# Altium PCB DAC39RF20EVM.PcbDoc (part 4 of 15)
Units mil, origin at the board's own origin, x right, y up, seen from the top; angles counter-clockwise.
Board outline 6200 x 2716.54 mil, 16 copper layers (Top Layer, L2 GND, L3 PWR, L4 GND, L5 PWR, L6 GND, L7 SIG, L8 GND, L9 GND, L10 SIG, L11 GND, L12 PWR, L13 GND, L14 PWR, L15 GND, Bottom Layer), stack 76.97 mil thick; 766 components, 495 nets, 3414 pads, 2373 vias.
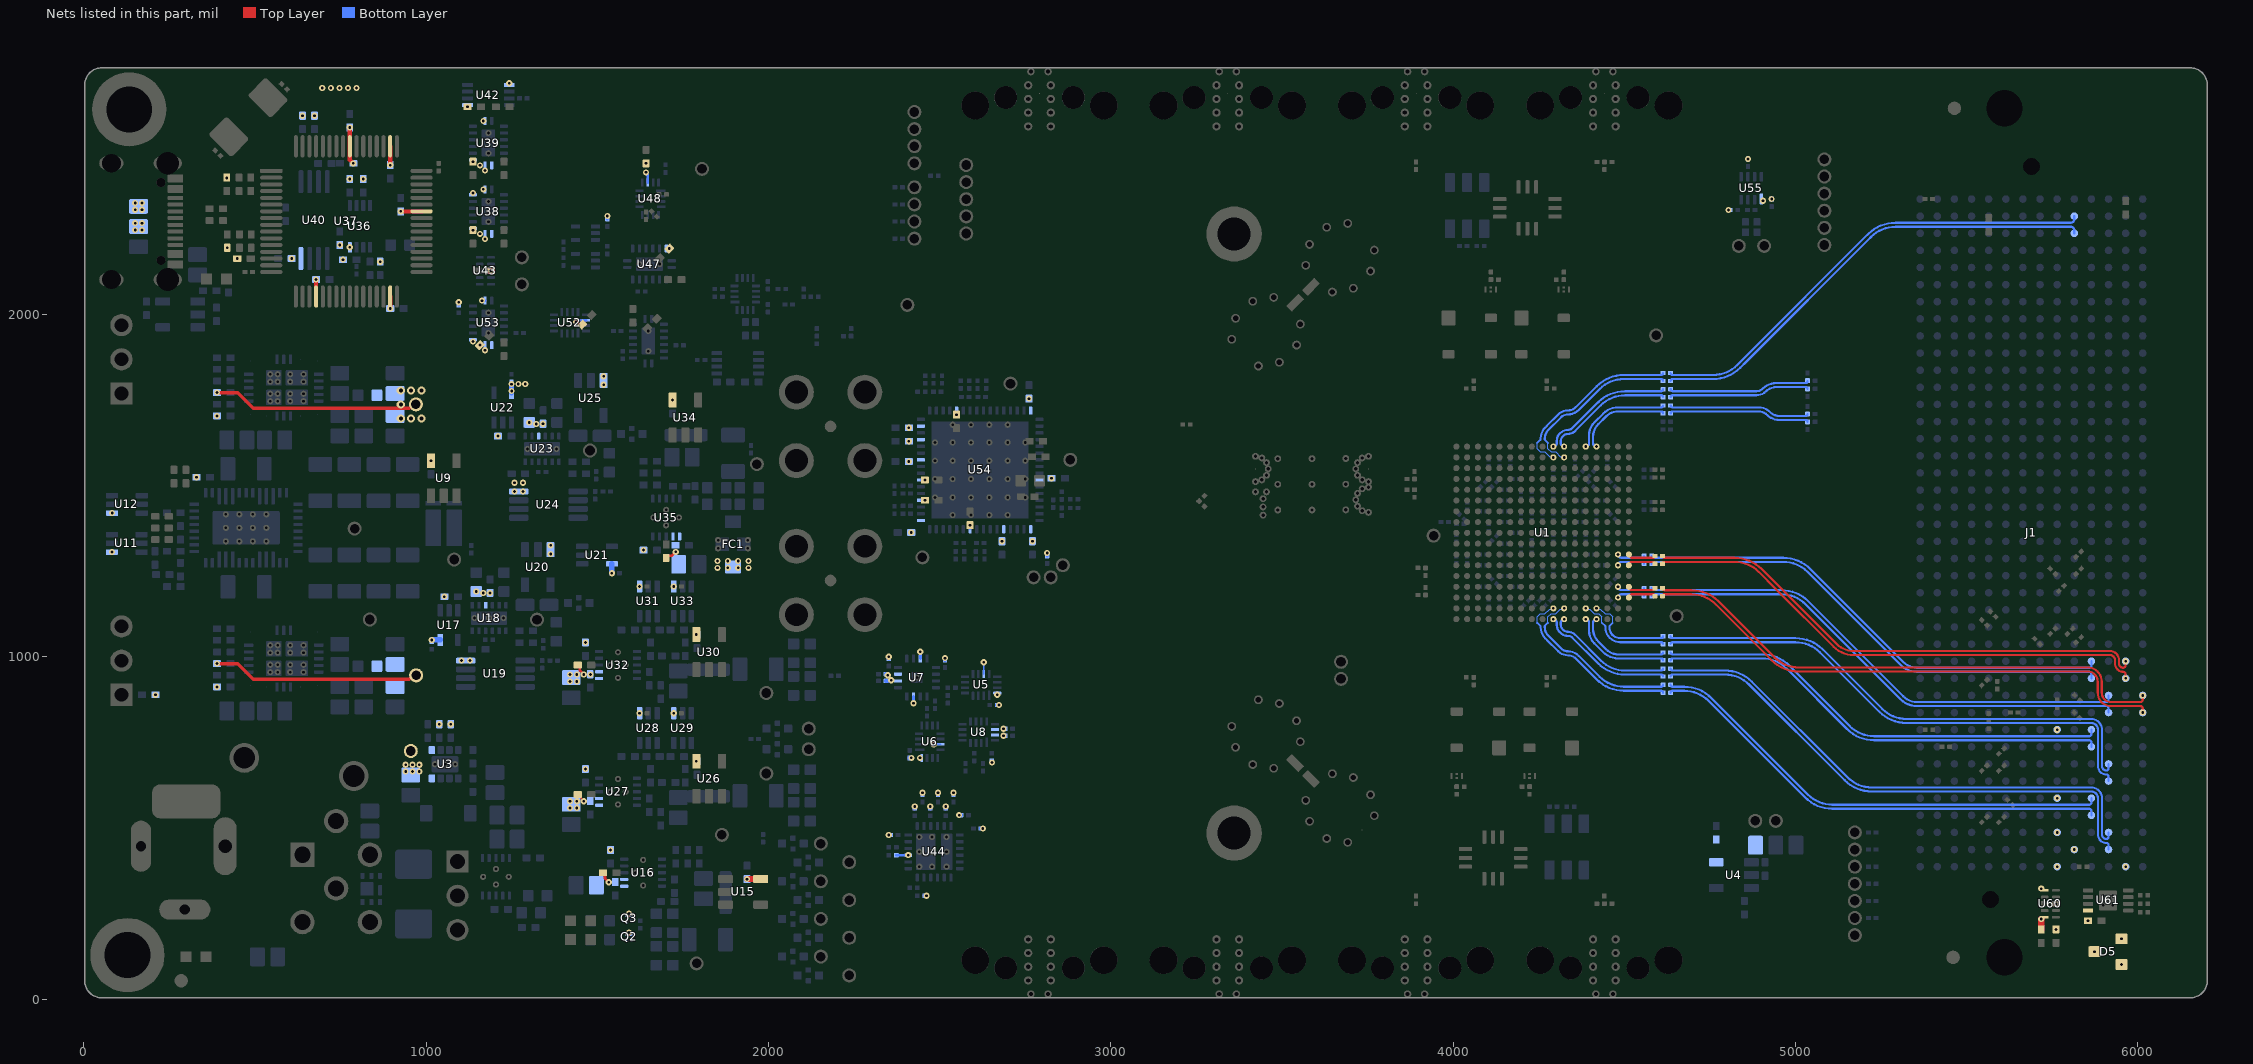
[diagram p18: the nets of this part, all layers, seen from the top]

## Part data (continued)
R6 R7 R104 R115 R116: library part RSMD080510615, "RES SMD 0 OHM JUMPER 1/8W 0805", Manufacturer="Panasonic Electronic Components", Operating Temperature="-55°C ~ 155°C", Power (Watts)="0.125W, 1/8W", Ratings=AEC-Q200, Resistance="0 Ω", Supplier Part Number 1=P0.0ACT-ND, Temperature Coefficient=-, Tolerance=Jumper
R10: library part RSMD040202418, "RES SMD 37.4KOHM 0.1% 1/16W 0402", Manufacturer="Panasonic Electronic Components", Operating Temperature="-55°C ~ 155°C", Power (Watts)="0.063W, 1/16W", Ratings=AEC-Q200, Resistance="37.4 kΩ", Supplier Part Number 1=P37.4KDCCT-ND, Temperature Coefficient=±25ppm/°C, Tolerance=±0.1%
R11: library part RSMD040200519, "RES SMD 12K OHM 1% 1/10W 0402", Manufacturer="Panasonic Electronic Components", Operating Temperature="-55°C ~ 155°C", Power (Watts)="0.1W, 1/10W", Ratings=AEC-Q200, Resistance="12 kΩ", Supplier Part Number 1=P12.0KLCT-ND, Temperature Coefficient=±100ppm/°C, Tolerance=±1%
R12 R16 R22 R43 R58 R66 R67 R78 R89 R178 R180: library part RSMD020100289, "RES SMD 100 OHM 1% 1/20W 0201", Manufacturer="Panasonic Electronic Components", Operating Temperature="-55°C ~ 125°C", Power (Watts)="0.05W, 1/20W", Resistance="100 Ω", Supplier Part Number 1=P122654CT-ND, Temperature Coefficient=±200ppm/°C, Tolerance=±1%
R13 R14 R15 R17 R18 R19 R128 R129 R130 R131 R132 R133 R134 R138 R139 R140 R142 R143 R144 R145 R148 R149 R151 R152 R154 R155 R156: library part RSMD020100762, "RES SMD 10K OHM 1% 1/20W 0201", Manufacturer="Panasonic Electronic Components", Operating Temperature="-55°C ~ 125°C", Power (Watts)="0.05W, 1/20W", Resistance="10 kΩ", Supplier Part Number 1=P122414CT-ND, Temperature Coefficient=±200ppm/°C, Tolerance=±1%
R21: library part RSMD040200358, "RES SMD 100K OHM 1% 1/10W 0402", Manufacturer="Panasonic Electronic Components", Operating Temperature="-55°C ~ 155°C", Power (Watts)="0.1W, 1/10W", Ratings=AEC-Q200, Resistance="100 kΩ", Supplier Part Number 1=P100KLCT-ND, Temperature Coefficient=±100ppm/°C, Tolerance=±1%
R23: library part CMP-0089456-1, "5 mOhms ±1% 1W Chip Resistor Wide 1206 (3216 Metric), 0612 Automotive AEC-Q200, Current Sense Metal Foil", Digikey Part Number=408-1969-1-ND, Manufacturer=Susumu, Mouser Part Number=754-KRL3216TMR005FT1, Operating Temperature Range="-55°C to +155°C", Power_W=1W, TempCo=50ppm/°C, Tolerance_%=1%
R24: library part RSMD040201279, "RES SMD 2.55KOHM 0.1% 1/16W 0402", Manufacturer="Panasonic Electronic Components", Operating Temperature="-55°C ~ 155°C", Power (Watts)="0.063W, 1/16W", Ratings=AEC-Q200, Resistance="2.55 kΩ", Supplier Part Number 1=P17782CT-ND, Temperature Coefficient=±15ppm/°C, Tolerance=±0.1%
R25: library part RSMD040200723, "RES SMD 14K OHM 1% 1/10W 0402", Manufacturer="Panasonic Electronic Components", Operating Temperature="-55°C ~ 155°C", Power (Watts)="0.1W, 1/10W", Ratings=AEC-Q200, Resistance="14 kΩ", Supplier Part Number 1=P14.0KLCT-ND, Temperature Coefficient=±100ppm/°C, Tolerance=±1%
R27: library part RSMD040200350, "RES SMD 10.7K OHM 1% 1/10W 0402", Manufacturer="Panasonic Electronic Components", Operating Temperature="-55°C ~ 155°C", Power (Watts)="0.1W, 1/10W", Ratings=AEC-Q200, Resistance="10.7 kΩ", Supplier Part Number 1=P10.7KLCT-ND, Temperature Coefficient=±100ppm/°C, Tolerance=±1%
R28: library part RSMD040200983, "RES SMD 17.4K OHM 1% 1/10W 0402", Manufacturer="Panasonic Electronic Components", Operating Temperature="-55°C ~ 155°C", Power (Watts)="0.1W, 1/10W", Ratings=AEC-Q200, Resistance="17.4 kΩ", Supplier Part Number 1=P17.4KLCT-ND, Temperature Coefficient=±100ppm/°C, Tolerance=±1%
R29: library part RSMD040201204, "RES SMD 2.2K OHM 0.1% 1/16W 0402", Manufacturer="Panasonic Electronic Components", Operating Temperature="-55°C ~ 155°C", Power (Watts)="0.063W, 1/16W", Ratings=AEC-Q200, Resistance="2.2 kΩ", Supplier Part Number 1=P2.2KCPCT-ND, Temperature Coefficient=±10ppm/°C, Tolerance=±0.1%
R30: library part RSMD040200908, "RES SMD 16.9KOHM 0.1% 1/16W 0402", Manufacturer="Panasonic Electronic Components", Operating Temperature="-55°C ~ 155°C", Power (Watts)="0.063W, 1/16W", Ratings=AEC-Q200, Resistance="16.9 kΩ", Supplier Part Number 1=P17956CT-ND, Temperature Coefficient=±10ppm/°C, Tolerance=±0.1%
R31 R74 R81: library part RSMD040200022, "RES SMD 1M OHM 1% 1/5W 0402", Manufacturer="Panasonic Electronic Components", Operating Temperature="-55°C ~ 155°C", Power (Watts)="0.2W, 1/5W", Ratings=AEC-Q200, Resistance="1 MΩ", Supplier Part Number 1=P17242CT-ND, Temperature Coefficient=±100ppm/°C, Tolerance=±1%
R32: library part RSMD040201457, "RES SMD 22K OHM 0.1% 1/16W 0402", Manufacturer="Panasonic Electronic Components", Operating Temperature="-55°C ~ 155°C", Power (Watts)="0.063W, 1/16W", Ratings=AEC-Q200, Resistance="22 kΩ", Supplier Part Number 1=P22KCNCT-ND, Temperature Coefficient=±15ppm/°C, Tolerance=±0.1%
R35: library part RSMD040203923, "RES SMD 9.31KOHM 0.1% 1/16W 0402", Manufacturer="Panasonic Electronic Components", Operating Temperature="-55°C ~ 155°C", Power (Watts)="0.063W, 1/16W", Ratings=AEC-Q200, Resistance="9.31 kΩ", Supplier Part Number 1=P9.31KDCCT-ND, Temperature Coefficient=±25ppm/°C, Tolerance=±0.1%
R36 R41: library part RSMD040203748, "RES SMD 80.6K OHM 1% 1/10W 0402", Manufacturer="Panasonic Electronic Components", Operating Temperature="-55°C ~ 155°C", Power (Watts)="0.1W, 1/10W", Ratings=AEC-Q200, Resistance="80.6 kΩ", Supplier Part Number 1=P80.6KLCT-ND, Temperature Coefficient=±100ppm/°C, Tolerance=±1%
R37 R42: library part RSMD040202615, "RES SMD 4.87KOHM 0.1% 1/16W 0402", Manufacturer="Panasonic Electronic Components", Operating Temperature="-55°C ~ 155°C", Power (Watts)="0.063W, 1/16W", Ratings=AEC-Q200, Resistance="4.87 kΩ", Supplier Part Number 1=P4.87KDCCT-ND, Temperature Coefficient=±25ppm/°C, Tolerance=±0.1%
R40: library part RSMD040201045, "RES SMD 18.2KOHM 0.1% 1/16W 0402", Manufacturer="Panasonic Electronic Components", Operating Temperature="-55°C ~ 155°C", Power (Watts)="0.063W, 1/16W", Ratings=AEC-Q200, Resistance="18.2 kΩ", Supplier Part Number 1=P17962CT-ND, Temperature Coefficient=±10ppm/°C, Tolerance=±0.1%
R46 R83 R92: library part OtherRs00003, "RES 0.01 OHM 1% 1/3W 0603", Manufacturer="Stackpole Electronics Inc", Operating Temperature="-55°C ~ 150°C", Power (Watts)="0.333W, 1/3W", Ratings=AEC-Q200, Resistance="10 mΩ", Supplier Part Number 1=738-CSS0603FT10L0CT-ND, Temperature Coefficient=±50ppm/°C, Tolerance=±1%
R47 R71 R77 R84 R85: library part RSMD040203878, "RES SMD 88.7KOHM 0.1% 1/16W 0402", Manufacturer="Panasonic Electronic Components", Operating Temperature="-55°C ~ 155°C", Power (Watts)="0.063W, 1/16W", Ratings=AEC-Q200, Resistance="88.7 kΩ", Supplier Part Number 1=P88.7KDCCT-ND, Temperature Coefficient=±25ppm/°C, Tolerance=±0.1%
R48 R94: library part RSMD040200551, "RES SMD 12.4KOHM 0.1% 1/16W 0402", Manufacturer="Panasonic Electronic Components", Operating Temperature="-55°C ~ 155°C", Power (Watts)="0.063W, 1/16W", Ratings=AEC-Q200, Resistance="12.4 kΩ", Supplier Part Number 1=P12.4KDCCT-ND, Temperature Coefficient=±25ppm/°C, Tolerance=±0.1%
R49: library part Resistor, "RES 12K OHM 0.5% 1/10W 0402 SMD", Manufacturer="Panasonic Electronic Components", Operating Temperature="-55°C ~ 155°C", Power (Watts)="0.1W, 1/10W", Ratings=AEC-Q200, Resistance="12 kΩ", Supplier Part Number 1=10-ERJ-U2RD1202XCT-ND, Temperature Coefficient=±50ppm/°C, Tolerance=±0.5%
R50 R76 R88 R96: library part RSMD040200004, "RES 0 OHM JUMPER 0402 SMD", Manufacturer="Panasonic Electronic Components", Operating Temperature="-55°C ~ 155°C", Power (Watts)="0.1W, 1/10W", Ratings=AEC-Q200, Resistance="0 Ω", Supplier Part Number 1=10-ERJ-U020R00XCT-ND, Temperature Coefficient="-100/ +600ppm/°C", Tolerance=Jumper
R51 R55 R59 R63 R169 R170: library part RSMD040200316, "RES 10K OHM 1% 1/10W 0402", Manufacturer="Panasonic Electronic Components", Operating Temperature="-55°C ~ 175°C", Power (Watts)="0.1W, 1/10W", Ratings=AEC-Q200, Resistance="10 kΩ", Supplier Part Number 1=10-ERJ-H2RF1002XCT-ND, Temperature Coefficient=±100ppm/°C, Tolerance=±1%
R52 R60 R70: library part OtherRs00006, "RES 0.005 OHM 1% 1/3W 0603", Manufacturer="Stackpole Electronics Inc", Operating Temperature="-55°C ~ 150°C", Power (Watts)="0.333W, 1/3W", Ratings=AEC-Q200, Resistance="5 mΩ", Supplier Part Number 1=CSS0603FT5L00-ND, Temperature Coefficient=±50ppm/°C, Tolerance=±1%
R53 R61: library part RSMD040201705, "RES SMD 25.5K OHM 1% 1/10W 0402", Manufacturer="Panasonic Electronic Components", Operating Temperature="-55°C ~ 155°C", Power (Watts)="0.1W, 1/10W", Ratings=AEC-Q200, Resistance="25.5 kΩ", Supplier Part Number 1=P25.5KLCT-ND, Temperature Coefficient=±100ppm/°C, Tolerance=±1%
R54 R57 R62 R65 R176 R177: library part RSMD020100735, "RES 10K OHM 1% 1/20W 0201 SMD", Manufacturer="Panasonic Electronic Components", Operating Temperature="-55°C ~ 125°C", Power (Watts)="0.05W, 1/20W", Resistance="10 kΩ", Supplier Part Number 1=10-ERJ-U01F1002CCT-ND, Temperature Coefficient=±200ppm/°C, Tolerance=±1%
R56 R64: library part RSMD040202910, "RES SMD 49.9K OHM 1% 1/10W 0402", Manufacturer="Panasonic Electronic Components", Operating Temperature="-55°C ~ 155°C", Power (Watts)="0.1W, 1/10W", Ratings=AEC-Q200, Resistance="49.9 kΩ", Supplier Part Number 1=P49.9KLCT-ND, Temperature Coefficient=±100ppm/°C, Tolerance=±1%
R72 R80: library part RSMD040202949, "RES SMD 5.23KOHM 0.1% 1/16W 0402", Manufacturer="Panasonic Electronic Components", Operating Temperature="-55°C ~ 155°C", Power (Watts)="0.063W, 1/16W", Ratings=AEC-Q200, Resistance="5.23 kΩ", Supplier Part Number 1=P18083CT-ND, Temperature Coefficient=±10ppm/°C, Tolerance=±0.1%
R73 R86: library part RSMD040202236, "RES SMD 33.2KOHM 0.1% 1/16W 0402", Manufacturer="Panasonic Electronic Components", Operating Temperature="-55°C ~ 155°C", Power (Watts)="0.063W, 1/16W", Ratings=AEC-Q200, Resistance="33.2 kΩ", Supplier Part Number 1=P33.2KDCCT-ND, Temperature Coefficient=±25ppm/°C, Tolerance=±0.1%
R75: library part RSMD040203275, "RES SMD 6.65KOHM 0.1% 1/16W 0402", Manufacturer="Panasonic Electronic Components", Operating Temperature="-55°C ~ 155°C", Power (Watts)="0.063W, 1/16W", Ratings=AEC-Q200, Resistance="6.65 kΩ", Supplier Part Number 1=P6.65KDCCT-ND, Temperature Coefficient=±25ppm/°C, Tolerance=±0.1%
R87: library part RSMD040202954, "RES SMD 5.36KOHM 0.1% 1/16W 0402", Manufacturer="Panasonic Electronic Components", Operating Temperature="-55°C ~ 155°C", Power (Watts)="0.063W, 1/16W", Ratings=AEC-Q200, Resistance="5.36 kΩ", Supplier Part Number 1=P5.36KDCCT-ND, Temperature Coefficient=±25ppm/°C, Tolerance=±0.1%
R93: library part RSMD040200995, "RES SMD 174K OHM 1% 1/10W 0402", Manufacturer="Panasonic Electronic Components", Operating Temperature="-55°C ~ 155°C", Power (Watts)="0.1W, 1/10W", Ratings=AEC-Q200, Resistance="174 kΩ", Supplier Part Number 1=P174KLCT-ND, Temperature Coefficient=±100ppm/°C, Tolerance=±1%
R95: library part RSMD040201463, "RES SMD 22K OHM 0.1% 1/16W 0402", Manufacturer="Panasonic Electronic Components", Operating Temperature="-55°C ~ 155°C", Power (Watts)="0.063W, 1/16W", Ratings=AEC-Q200, Resistance="22 kΩ", Supplier Part Number 1=P22KDCCT-ND, Temperature Coefficient=±25ppm/°C, Tolerance=±0.1%
R98 R101: library part RSMD040202594, "RES SMD 4.7K OHM 1% 1/10W 0402", Manufacturer="Panasonic Electronic Components", Operating Temperature="-55°C ~ 155°C", Power (Watts)="0.1W, 1/10W", Ratings=AEC-Q200, Resistance="4.7 kΩ", Supplier Part Number 1=P4.70KLCT-ND, Temperature Coefficient=±100ppm/°C, Tolerance=±1%
R99 R102 R107 R135 R136 R137 R171 R172 R173 R174 R181 R182 R183 R184 R185 R186 R187 R188 R189 R190 R191 R192 R193 R198 R199 R200 R201 R202 R203 R204 R205 R206 R207 R208 R209 R210 R211 R212 R213 R214 R215 R216 R217 R218 R219 R221 R222 R223 R224 R225 R226 R227 R228 R230 R231 R232 R233 R234 R237 R238 R239 R240 R241 R242 R243 R244 R245 R246 R247 R248 R249 R250 R251 R252 R253: library part RSMD020101699, "RES SMD 0 OHM JUMPER 1/20W 0201", Manufacturer="Panasonic Electronic Components", Operating Temperature="-55°C ~ 125°C", Power (Watts)="0.05W, 1/20W", Resistance="0 Ω", Supplier Part Number 1=P15979CT-ND, Tolerance=Jumper
R103 R220 R229: library part RSMD040200375, "RES SMD 100 OHM 1% 1/10W 0402", Manufacturer="Panasonic Electronic Components", Operating Temperature="-55°C ~ 155°C", Power (Watts)="0.1W, 1/10W", Ratings=AEC-Q200, Resistance="100 Ω", Supplier Part Number 1=P100LCT-ND, Temperature Coefficient=±100ppm/°C, Tolerance=±1%
R105 R106 R109: library part RSMD040200327, "RES SMD 10 OHM 5% 1/10W 0402", Manufacturer="Panasonic Electronic Components", Operating Temperature="-55°C ~ 155°C", Power (Watts)="0.1W, 1/10W", Ratings=AEC-Q200, Resistance="10 Ω", Supplier Part Number 1=P10JCT-ND, Temperature Coefficient=±200ppm/°C, Tolerance=±5%
R108 R114 R117: library part RSMD040201206, "RES SMD 2.2K OHM 5% 1/10W 0402", Manufacturer="Panasonic Electronic Components", Operating Temperature="-55°C ~ 155°C", Power (Watts)="0.1W, 1/10W", Ratings=AEC-Q200, Resistance="2.2 kΩ", Supplier Part Number 1=P2.2KJCT-ND, Temperature Coefficient=±200ppm/°C, Tolerance=±5%
R110: library part RSMD040200523, "RES SMD 12K OHM 5% 1/10W 0402", Manufacturer="Panasonic Electronic Components", Operating Temperature="-55°C ~ 155°C", Power (Watts)="0.1W, 1/10W", Ratings=AEC-Q200, Resistance="12 kΩ", Supplier Part Number 1=P12KJCT-ND, Temperature Coefficient=±200ppm/°C, Tolerance=±5%
R119 R120 R121 R122 R123 R124 R125 R126 R127: library part RSMD020100508, "RES SMD 4.7K OHM 1% 1/20W 0201", Manufacturer="Panasonic Electronic Components", Operating Temperature="-55°C ~ 125°C", Power (Watts)="0.05W, 1/20W", Resistance="4.7 kΩ", Supplier Part Number 1=P123031CT-ND, Temperature Coefficient=±200ppm/°C, Tolerance=±1%
R141 R146 R147 R150 R153 R157 R161 R168: library part RSMD020100177, "RES SMD 49.9 OHM 1% 1/20W 0201", Manufacturer="Panasonic Electronic Components", Operating Temperature="-55°C ~ 125°C", Power (Watts)="0.05W, 1/20W", Resistance="49.9 Ω", Supplier Part Number 1=P123049CT-ND, Temperature Coefficient=±200ppm/°C, Tolerance=±1%
R158 R162 R163 R164 R165: library part RSMD020101357, "RES 560 OHM 5% 1/20W 0201 SMD", Manufacturer="Panasonic Electronic Components", Operating Temperature="-55°C ~ 125°C", Power (Watts)="0.05W, 1/20W", Resistance="560 Ω", Supplier Part Number 1=10-ERJ-U01J561CCT-ND, Temperature Coefficient=±200ppm/°C, Tolerance=±5%
R159 R160 R166 R167: library part RSMD020100105, "RES SMD 240 OHM 1% 1/20W 0201", Manufacturer="Panasonic Electronic Components", Operating Temperature="-55°C ~ 125°C", Power (Watts)="0.05W, 1/20W", Resistance="240 Ω", Supplier Part Number 1=P122856CT-ND, Temperature Coefficient=±200ppm/°C, Tolerance=±1%
R175: library part RSMD020100620, "RES SMD 3.6K OHM 1% 1/20W 0201", Manufacturer="Panasonic Electronic Components", Operating Temperature="-55°C ~ 125°C", Power (Watts)="0.05W, 1/20W", Resistance="3.6 kΩ", Supplier Part Number 1=P122962CT-ND, Temperature Coefficient=±200ppm/°C, Tolerance=±1%
R179: library part RSMD020100143, "RES SMD 1K OHM 1% 1/20W 0201", Manufacturer="Panasonic Electronic Components", Operating Temperature="-55°C ~ 125°C", Power (Watts)="0.05W, 1/20W", Resistance="1 kΩ", Supplier Part Number 1=P122413CT-ND, Temperature Coefficient=±200ppm/°C, Tolerance=±1%
R195 R196 R197: library part RSMD020101186, "RES SMD 10K OHM 5% 1/20W 0201", Manufacturer="Panasonic Electronic Components", Operating Temperature="-55°C ~ 125°C", Power (Watts)="0.05W, 1/20W", Resistance="10 kΩ", Supplier Part Number 1=P123222CT-ND, Temperature Coefficient=±200ppm/°C, Tolerance=±5%
R235 R236: library part RSMD060311096, "RES SMD 330 OHM 5% 1/10W 0603", Manufacturer="Panasonic Electronic Components", Operating Temperature="-55°C ~ 155°C", Power (Watts)="0.1W, 1/10W", Ratings=AEC-Q200, Resistance="330 Ω", Supplier Part Number 1=P330GCT-ND, Temperature Coefficient=±200ppm/°C, Tolerance=±5%
SW1: library part cmp00460, "SWITCH SLIDE SPDT 3A 120V", Alt Manufacturer=-, Current Rating (Amps)=3A, Manufacturer=E-Switch, Supplier Part Number 1=EG2481-ND, Voltage Rating - DC=120V
SW2 SW3: "Switch Slide SPDT 12V, 500mA", Alt Manufacturer=-, Manufacturer="Wurth Elektronik", PartNumber=450301014042, Supplier Part Number 1=710-450301014042
T1: library part cmp00464, "Balun, 10 to 32000 MHz, 1 W Pwr Handling, 8 dB IL, +/- 0.5 dB Amp. Var,", Alt Manufacturer=-, Manufacturer="Marki Microwave"
T2 T4 T6 T8: "MINIATURE SURFACE-MOUNT BIAS-TEE", Alt Manufacturer=-, Manufacturer=MiniCircuits, Supplier Part Number 1=3157-TCBT-203+-ND
T3 T7: library part cmp00461, "1:2 MMIC Transformer, 2 - 18 GHz, 50Ω", Alt Manufacturer=-, Manufacturer=Mini-Circuits
T5 T9: "1:1 Transmission Line Balun / 5 MHz - 10GHz", Manufacturer=MACOM, Supplier Part Number 1=937-MABA-011108
TP1: library part cmp00040, "Test Point, Multipurpose, Red, TH", Alt Manufacturer=-, Color=Red, Manufacturer=Keystone, Supplier Part Number 1=36-5010-ND
TP2: library part cmp00047, "Test Point, Multipurpose, Brown, TH", Alt Manufacturer=-, Color=Brown, Manufacturer=Keystone, Supplier Part Number 1=36-5125-ND
U1: library part cmp00515, Alt Manufacturer=-, Color=BGA-289, Manufacturer="Texas Instruments"
U2: library part cmp00157, "12V, 5A, 30mΩ eFuse with Adjustable +/-15% Accurate Current Limit, DRC0010J (VSON-10)", Alt Manufacturer=-, Manufacturer="Texas Instruments"
U3: "17V Input 2A Synchronous Step-Down Converter MicroSiP Module With Integrated Inductor, SIL0008D (uSIP-8)", Alternate Manufacturer="Texas Instruments", Alternate PartNumber=TPS82140SILT
U4: "150-mA, 30-V, ultra-low-IQ, low-dropout voltage regulator with reverse current protection and enable", Alt Manufacturer=-, Manufacturer="Texas Instruments", Supplier Part Number 1=296-35484-1-ND
U5 U6: library part TMUX1108RSV, "3-pA on-state leakage current, 5-V, 8:1, 1-channel precision multiplexer", Alt Manufacturer=-, Manufacturer="Texas Instruments", Supplier Part Number 1=296-53257-2-ND
U7: library part ADS1119IRTER, "16-Bit, 4-Channel, 1-kSPS, Delta-Sigma ADC with I2C Interface, RTE0016D (WQFN-16)", Alternate Manufacturer="Texas Instruments", Operating Temperature Range="-40 to 125 C"
U8: library part cmp00387, "8-bit translating 1.65- to 5.5-V I2C/SMBus I/O expander with interrupt, reset & config registers", Alt Manufacturer=-, Manufacturer="Texas Instruments"
U9 U15 U26 U30 U34: "26V, 350kHz current sense amplifier", Alt Manufacturer="Texas Instruments", Alt PartNumber=INA180B1IDBVT
U10: library part cmp00235, "4.5-V to 15-V Input, Dual 6-A / Single 12-A Output Power Module", Alt Manufacturer=-, Manufacturer="Texas Instruments", Supplier Part Number 1=296-TPSM5D1806RDBRCT-ND
U11 U28 U31: library part cmp00230, "128-tap single-channel digital potentiometer (digipot) with I2C interface (address 0101110)", Alt Manufacturer=-, Alternate Manufacturer="Texas Instruments", Alternate PartNumber=TPL0401A-10DCKT
U12 U29 U33: library part cmp00231, "128-tap single-channel digital potentiometer (digipot) with I2C interface (address 0111110)", Alt Manufacturer=-, Alternate Manufacturer="Texas Instruments", Alternate PartNumber=TPL0401A-10DCKT
U13 U14: library part cmp00201, "3-V to 17-V, 3-A Low-Noise and Low-Ripple Buck Power Module with Integrated Ferrite Bead Filter Compensation", Alt Manufacturer=-, Manufacturer="Texas Instruments", Max Supply Voltage=17V, Min Supply Voltage=3V, Nominal Supply Current=5mA, Operating Temperature Range="-55°C to +125°C", Output Voltage=0.8-5.5V, Part Number=TPSM82913RDUR, Switching Frequency=1/2.2MHz
U16 U27 U32 U35: library part cmp00446, "2-A, ultra-low noise ultra-high PSRR RF voltage regulator", Alt Manufacturer=-, Manufacturer="Texas Instruments", PartNumber=TPS7A9601DSCR
U17 U22: library part cmp00128, "Single Bus Inverting Buffer Gate", Alt Manufacturer=-, Manufacturer="Texas Instruments"
U18 U23: library part cmp00189, "Low-Noise Positive- and Negative-Output Charge Pump With Integrated LDO", Alt Manufacturer=-, Manufacturer="Texas Instruments"
U19 U24: Manufacturer="Texas Instruments"
U20 U25: library part INA293B1IDBV, "INA293 High-Voltage, High Bandwidth, Unidirectional, 110-V Common-Mode, Current-Sense Amplifier, DBV0005A (SOT-23-5)", Alternate Manufacturer="Texas Instruments", Alternate PartNumber=INA293B1IDBVT
U21: library part cmp00268, "SN74AUP1G08 Low-Power Single 2-Input Positive-AND Gate", Color=-, Manufacturer="Texas Instruments", Supplier Part Number 1=296-19075-1-ND
U36: "Dual Bus Buffer Gate with 3-State Outputs, DCU0008A (VSSOP-8)", F @ Nom Voltage(Max)(Mhz)=150, Generic Part Number=SN74LVC2G125, ICC @ Nom Voltage(Max)(mA)=0.01, Manufacturer="Texas Instruments", Operating Temperature Range="-40 to 125 C", Rating=Catalog, tpd @ Nom Voltage(Max)(ns)=9.1,4.8,4.3,3.7, Voltage(Nom)(V)=1.8,2.5,3.3,5
U37: library part cmp00204, "USB Interface IC USB HS to Quad UART/ SPI/JTAG/I2C LQFP-6", Alt Manufacturer=FTDI, Alt PartNumber=FT4232HL-TRAY, Color=-, Supplier Part Number 1=768-1026-1-ND
U38 U39 U47 U49 U53: library part cmp00170, "Translation - Voltage Levels 4-bit dual-supply bus transceiver with 3-state outputs and independent direction control inputs", Alt Manufacturer="Texas Instruments", Alt PartNumber=SN74AXC4T774BQB, Color=-
U40: library part cmp00156, "1K Microwire Compatible Serial EEPROM", Alt Manufacturer=-, Manufacturer="Microchip Technology", Supplier Part Number 1=93LC46B-I/ST-ND
U41: library part cmp00162, "300-mA, high-PSRR, low-IQ, low-dropout voltage regulator with enable", Alt Manufacturer=-, Manufacturer="Texas Instruments"
U42 U45: library part cmp00175, "Dual-Bit Dual-Supply Bus Transceiver With Configurable Voltage Translation And 3-State Outputs", Alt Manufacturer="Texas Instruments", Alt PartNumber=SN74AXCH2T45DCU, Color=-
U43 U60: library part cmp00307, "5-V low-leakage-current, 2: 1, 2-channel precision analog switch", Alt Manufacturer=-, Manufacturer="Texas Instruments", PartNumber=TMUX1136DQA, Supplier Part Number 1=296-TMUX1136DQARCT-ND
U44: library part TCA9548ARGE, "Low-Voltage 8-Channel I2C Switch With Reset, RGE0024C (VQFN-24)", Alternate Manufacturer="Texas Instruments", Operating Temperature Range="-40 to 85 C"
U46: library part cmp00171, "Translation - Voltage Levels 4-bit dual-supply bus transceiver with 3-state outputs and independent direction control inputs", Alt Manufacturer="Texas Instruments", Alt PartNumber=SN74AXC4T774RSV, Color=-, Supplier Part Number 1=296-24741-1-ND
U48 U52: library part SN74CBTLV3257RSV, "Low-Voltage 4-Bit 1-of-2 FET Multiplexer/Demultiplexe", Color=-, Manufacturer="Texas Instruments", PartNumber=SN74CBTLV3257RSVR, Supplier Part Number 1=296-35586-1-ND
U50 U51: "Single Bus Buffer Gate With 3-State Outputs", Alt Manufacturer=-, Manufacturer="Texas Instruments"
U54: "Ultra low-noise JESD204B compliant clock jitter cleaner with integrated 2370 to 2630-MHz VCO0", Alt Manufacturer="Texas Instruments", Alt PartNumber=LMK04828BISQE/NOPB, Color=-, Supplier Part Number 1=296-40278-1-ND
U55: library part TMP451AIDQF, "1.7V-Capable Remote and Local Temp Sensor with Auto Beta, N-Factor, Filter, and Series-R Correction, DQF0008A (WSON-8)", Alternate Manufacturer="Texas Instruments", Alternate PartNumber=TMP451AIDQFT
U56 U57 U58 U59: "RF Attenuators 3dB 0 Hz ~ 50 GHz 50 Ohms 32mW 0402 (1005 Metric)", Manufacturer=Susumu, Supplier Part Number 1=408-ATS1005-3DB-FD-T05CT-ND
U61: library part cmp00154, "EEPROM 64K 8KX8 1.8V SER EE IND 1/4AWP RPO", Alt Manufacturer=-, Manufacturer=Microchip, Supplier Part Number 1=24LC64FT-I/MNYCT-ND
Y1: library part cmp00323, "12 MHz ±20ppm Crystal 18pF 60 Ohms 2-SMD, No Lead", Alt Manufacturer=-, Manufacturer="Abracon LLC", Supplier Part Number 1=815-ABM3-12-D2Y-T

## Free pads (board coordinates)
  rrect50% 200x100 on Mid11 mask+1.97: 1(221.01,1674.63) 1(298.17,582.74) 1(992.61,1368.8) 1(2461.47,207.36) 1(5001.22,1375.07)
  rrect50% 200x100 on Mid5 mask+1.97: 1(242.86,1686.82) 1(282.86,1921.82) 1(296.26,581.46) 1(377.86,2596.82) 1(652.86,1381.82) 1(1337.86,721.82) 1(1936.7,144.81) 1(1947.86,2491.82) 1(2415,1930) 1(2807.86,1076.82) 1(3551.34,382.78)
  rrect50% 200x100 on Mid7 mask+1.97: 1(287.86,576.82) 1(942.86,1346.82) 1(1983.23,2478.31) 1(2552.86,216.82) 1(3073.23,1288.31)
  rrect50% 200x100 on Mid3 mask+1.97: 1(297.61,578.8)
  rrect50% 200x100 on Mid8 mask+1.97: 1(298.17,582.74) 1(927.86,1936.82) 1(2047.86,2551.82) 1(2157.86,1441.82) 1(2627.86,2026.82) 1(2920.33,1074.9) 1(3345.34,601.99) 1(3603.54,375.71) 1(3619.67,221.32)
  rrect50% 200x100 on Mid14 mask+1.97: 1(298.17,582.74)
  rrect50% 200x100 on Mid12 mask+1.97: 1(298.17,582.74)
  rrect50% 200x100 on Mid13 mask+1.97: 1(298.17,582.74)
  rrect50% 200x100 on Mid10 mask+1.97: 1(298.17,582.74)
  rrect50% 200x100 on Mid1 mask+1.97: 1(298.22,587.41)
  rrect50% 200x100 on Mid2 mask+1.97: 1(298.23,583.31) 1(1988.23,2488.31) 1(2940.17,477.52) 1(3598.23,258.31)
  rrect50% 200x100 smd mask+1.97: 1(299.17,577.65)
  rrect50% 200x100 on Mid4 mask+1.97: 1(299.17,582.83)
  rrect50% 200x100 on Mid9 mask+1.97: 1(299.44,582.74)
  rrect50% 200x100 on Mid6 mask+1.97: 1(304.72,582.83)
  rrect50% 75x50 on Mid5 mask+1.97: 1(647.86,2376.82)
  rrect50% 100x75 on Mid14 mask+1.97: 1(1216.95,1593.97)
  rrect50% 75x50 on Mid8 mask+1.97: 1(5822.61,178.8) 1(6037.61,123.8)

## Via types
v1: diameter 18, hole 8, Top Layer to Bottom Layer, tented both sides, 2344 vias
v2: diameter 24, hole 12, Top Layer to Bottom Layer, tented both sides, 19 vias
v3: diameter 18, hole 8, Top Layer to Bottom Layer, tented bottom, 9 vias
v4: diameter 20, hole 10, Top Layer to Bottom Layer, tented both sides, 1 vias

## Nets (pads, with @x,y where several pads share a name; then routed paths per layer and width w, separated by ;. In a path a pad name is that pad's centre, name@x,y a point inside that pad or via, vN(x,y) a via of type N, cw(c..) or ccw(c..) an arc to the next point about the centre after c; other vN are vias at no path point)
0SRX_DUT_n: C179.1 U1.A8 | length 395.4
  Bottom Layer w6.3: v1(4292.49,1110) cw(c4292.49,1100.15) 4302.34,1100.15 4302.34,1092.53 ccw(c4330.56,1092.53) 4310.61,1072.57 4312.91,1070.27 ccw(c4334.92,1092.28) 4334.92,1061.15 cw(c4334.92,1042.69) 4347.97,1055.75 4422.86,980.86 ccw(c4501.91,1059.92) 4501.91,948.12 4607.37,948.12 cw(c4607.37,942.52) C179.1@4612.97,942.52
0SRX_DUT_p: C178.1 U1.A7 | length 376.9
  Bottom Layer w6.3: v1(4323.99,1110) ccw(c4323.99,1100.15) 4314.14,1100.15 4314.14,1092.53 ccw(c4330.56,1092.53) 4318.95,1080.92 4321.26,1078.61 ccw(c4334.92,1092.28) 4334.92,1072.95 cw(c4334.92,1042.69) 4356.32,1064.09 4431.2,989.21 ccw(c4501.91,1059.92) 4501.91,959.92 4607.37,959.92 ccw(c4607.37,965.52) C178.1@4612.97,965.52
0SRX_n: C179.2 J1.A39 | length 1562.3
  Bottom Layer w6.3: C179.2@4635.01,942.52 cw(c4640.61,942.52) 4640.61,948.12 4793.31,948.12 cw(c4793.31,848.12) 4864.02,918.83 5143.38,639.47 ccw(c5222.44,718.52) 5222.44,606.72 5862.85,606.72 cw(c5862.85,586.34) 5873.57,603.67 5874.09,603.35 cw(c5864.01,587.07) 5883.13,588.23 5883.22,586.72 cw(c5876.93,586.34) 5883.23,586.34 5883.23,480.65 ccw(c5907.71,480.65) 5907.71,456.17 cw(c5907.71,449.86) 5914.01,449.86 J1.A39@5914.01,437.07
0SRX_p: C178.2 J1.A38 | length 1562.2
  Bottom Layer w6.3: C178.2@4635.01,965.52 ccw(c4640.61,965.52) 4640.61,959.92 4793.31,959.92 cw(c4793.31,848.12) 4872.37,927.17 5151.73,647.81 ccw(c5222.44,718.52) 5222.44,618.52 5862.85,618.52 cw(c5862.85,586.34) 5895.03,586.34 5895.03,480.65 ccw(c5907.71,480.65) 5907.71,467.97 ccw(c5907.71,474.27) 5914.01,474.27 J1.A38@5914.01,487.07
1SRX_DUT_n: C181.1 U1.B8 | length 530.2
  Bottom Layer w3.4: 4245.2,1098.95 4245.2,1116.64 4254.31,1125.75 4262.92,1125.75
  Bottom Layer w3.5: 4262.92,1125.75 4267.52,1125.75 4281.3,1139.53 4290.53,1139.53 v1(4292.49,1141.5)
  Bottom Layer w5.6: 4245.2,1098.95 4254.75,1090.15 4255.34,1089.56
  Bottom Layer w6.3: 4255.34,1089.56 4255.34,1086.03 ccw(c4300.3,1086.03) 4268.51,1054.24 4272.68,1050.06 ; 4273.46,1049.29 4306.76,1015.98 ; 4306.77,1015.97 ccw(c4335.09,1044.3) 4335.09,1004.25 cw(c4335.09,971.88) 4357.98,994.77 4419.23,933.52 ccw(c4498.28,1012.57) 4498.28,900.77 4607.36,900.77 cw(c4607.36,895.17) C181.1@4612.96,895.17
1SRX_DUT_p: C180.1 U1.B7 | length 512.3
  Bottom Layer w3.4: 4276.7,1098.95 4276.7,1116.64 4285.81,1125.75 4294.41,1125.75
  Bottom Layer w3.5: 4294.42,1125.75 4299.02,1125.75 4312.8,1139.53 4322.02,1139.53 v1(4323.99,1141.5)
  Bottom Layer w5.6: 4267.14,1089.64 4267.73,1090.24 4276.7,1098.95
  Bottom Layer w6.3: 4267.14,1089.64 4267.14,1086.03 ccw(c4300.3,1086.03) 4276.85,1062.58 4315.11,1024.33 ccw(c4335.09,1044.3) 4335.09,1016.05 cw(c4335.09,971.88) 4366.32,1003.11 4427.57,941.86 ccw(c4498.28,1012.57) 4498.28,912.57 4607.36,912.57 ccw(c4607.36,918.17) C180.1@4612.96,918.17
1SRX_n: C181.2 J1.B37 | length 1382.2
  Bottom Layer w6.3: C181.2@4635.01,895.17 cw(c4640.61,895.17) 4640.61,900.77 4674.82,900.77 cw(c4674.82,800.77) 4745.53,871.48 5028.1,588.91 ccw(c5107.16,667.97) 5107.16,556.17 5857.71,556.17 cw(c5857.71,549.86) 5864.01,549.86 J1.B37@5864.01,537.07
1SRX_p: C180.2 J1.B36 | length 1382.2
  Bottom Layer w6.3: C180.2@4635.01,918.17 ccw(c4640.61,918.17) 4640.61,912.57 4674.82,912.57 cw(c4674.82,800.77) 4753.87,879.83 5036.44,597.26 ccw(c5107.16,667.97) 5107.16,567.97 5857.71,567.97 ccw(c5857.71,574.27) 5864.01,574.27 J1.B36@5864.01,587.07
2p3V: C37.2 C38.2 C49.2 C50.2 C81.2 C82.2 C92.2 C93.2 FB1.2 pad.1@1337.86,721.82 PP12.1 R35.2 R45.2 R69.2 R82.2 U16.1 U16.2 U27.1 U27.2 U32.1 U32.2 | length 706.6
  Top Layer w5: R69.2@1442.73,597.86 1444.7,597.86 1452.04,590.51 1452.04,587.52 1460.2,579.36 v1(1460.2,578.09)
  Top Layer w8: R82.2@1442.73,975.86 1443.05,975.86 1448.89,970.01 1448.89,959.4 v1(1460.2,948.09) ; R45.2@1516.1,369.31 1516.42,369.31 1522.26,363.47 1522.26,352.85 v1(1533.57,341.54)
  Top Layer w10: v1(389.38,980.11) 449.31,980.11 495.19,934.23 950.99,934.23 962.56,945.8 PP12.1@970.86,945.8 PP12.1@973.63,945.8
  other v1: 1420.2,558.09 1440.2,558.09 1420.2,578.09 1440.2,578.09 1420.2,928.09 1440.2,928.09 1420.2,948.09 1440.2,948.09 1480.2,948.09
2SRX_DUT_n: C187.1 U1.A5 | length 300
  Bottom Layer w6.3: v1(4386.98,1110) cw(c4386.98,1100.15) 4396.83,1100.15 4396.83,1075.6 ccw(c4447.48,1075.6) 4411.66,1039.79 4437.81,1013.64 ccw(c4481.96,1057.81) 4481.96,995.36 4607.37,995.36 cw(c4607.37,989.76) C187.1@4612.97,989.76
2SRX_DUT_p: C185.1 U1.A4 | length 281
  Bottom Layer w6.3: v1(4418.48,1110) ccw(c4418.48,1100.15) 4408.63,1100.15 4408.63,1080.49 ccw(c4459.28,1080.49) 4423.46,1044.67 4446.14,1021.99 ccw(c4481.96,1057.81) 4481.96,1007.16 4607.37,1007.16 ccw(c4607.37,1012.76) C185.1@4612.97,1012.76
2SRX_n: C187.2 J1.B33 | length 1338.6
  Bottom Layer w6.3: C187.2@4635.01,989.76 cw(c4640.61,989.76) 4640.61,995.36 4902.53,995.36 cw(c4902.53,895.36) 4973.24,966.07 5150.39,788.91 ccw(c5229.45,867.97) 5229.45,756.17 5857.71,756.17 cw(c5857.71,749.86) 5864.01,749.86 J1.B33@5864.01,737.07
2SRX_p: C185.2 J1.B32 | length 1338.6
  Bottom Layer w6.3: C185.2@4635.01,1012.76 ccw(c4640.61,1012.76) 4640.61,1007.16 4902.53,1007.16 cw(c4902.53,895.36) 4981.58,974.41 5158.74,797.26 ccw(c5229.45,867.97) 5229.45,767.97 5857.71,767.97 ccw(c5857.71,774.27) 5864.01,774.27 J1.B32@5864.01,787.07
3p3V_AUX: D5.2 J1.D32
  other v1: 5951.96,176.2 5764.01,787.07
3p3V_Clock: C148.1 C149.1 C150.1 C151.1 C152.1 C153.1 C154.1 C155.1 C156.1 C157.1 C158.1 C159.1 FC1.3 pad.1@2157.86,1441.82 R138.1 U54.10 U54.17 U54.21 U54.26 U54.33 U54.36 U54.39 U54.42 U54.45 U54.47 U54.53 U54.64 | length 55.9
  Bottom Layer w5: U54.36@2444.96,1457.25 v1(2456.77,1457.25) ; U54.39@2444.96,1516.3 v1(2456.77,1516.3) ; v1(2549.29,1707.25) U54.53@2549.29,1719.06 ; U54.26@2588.66,1372.6 v1(2588.66,1384.41)
  Bottom Layer w8: R138.1@2813.86,1294.75 v1(2813.86,1303.41)
  other v1: 1851.28,1259.78 1881.28,1259.78 1911.28,1259.78 1941.28,1259.78 1851.28,1279.78 1881.28,1279.78 1911.28,1279.78 1941.28,1279.78 2682.16,1337.6 2770.74,1337.6 2416.96,1363.19 2826.41,1521.22 2409.96,1570.44 2409.96,1629.49 2409.96,1668.86 2760.9,1754.06
3p3V_EEPROM: C315.2 C316.2 D5.3 pad.1@5822.61,178.8 U60.8@5760.47,278.48 U61.8
  other v1: 5873.22,138.8 5760.47,203.8 5854.4,228.79 5760.47,278.48
3p3V_FMC: J1.C39 J1.D36 J1.D38 J1.D40 J1.Z40 pad.1@6037.61,123.8 R194.2 U60.1 U60.5 | length 58.6
  Top Layer w5: v1(5717.59,234.11) 5717.59,235.75 5717.05,235.75 5720.41,239.11 U60.5@5727.59,239.11 ; v1(5717.59,322.85) 5717.59,321.21 5717.05,321.21 5720.41,317.85 U60.1@5727.59,317.85
  Top Layer w18: R194.2@5717.59,203.8 v1(5717.59,234.11)
  other v1: 5764.01,387.07 5964.01,387.07 5814.01,437.07 5764.01,487.07 5764.01,587.07
3p3V_FTDI: C123.2 C124.2 C125.2 C126.2 C127.2 C128.2 FB7.1 FB8.1 pad.1@377.86,2596.82 R105.2 R111.2 R112.2 R113.2 R115.1 R116.2 U37.20 U37.31 U37.42 U37.50 U37.56 U40.8 | length 310.1
  Top Layer w12: U37.20@678.5,2052.12 v1(678.5,2102.12) ; v1(776.93,2546.1) U37.56@776.93,2491.1 776.93,2451.62 v1(787.25,2441.3) ; v1(895.04,2017.12) U37.31@895.04,2052.12 ; v1(895.04,2436.1) U37.50@895.04,2491.1 ; v1(925.57,2301.14) U37.42@986.57,2301.14
  other v1: 448.22,2163.34 607.21,2163.34 418.96,2194.67 149.94,2246.6 169.94,2246.6 149.94,2266.6 169.94,2266.6 417.61,2398.8 639.13,2580.47 673.81,2580.47
3p3V_Utility: C9.2 C13.1 C14.1 C15.1 C16.1 C17.1 C18.1 C19.2 C48.2 C65.2 C72.2 C73.2 C80.2 C91.2 C100.1 C101.1 C102.1 C103.1 C104.2 C113.2 C119.2 C121.2 C131.2 C135.2 C140.2 C142.1 C145.2 C146.2 C217.2 D5.1 pad.1@221.01,1674.63 pad.1@652.86,1381.82 pad.1@1216.95,1593.97 pad.1@2047.86,2551.82 pad.1@2461.47,207.36 PP1.1 Q2.3 Q3.3 R5.2 R10.2 R17.2 R18.2 R19.2 R20.2 R33.2 R38.2 R44.2 R51.2 R59.2 R68.2 R79.2 R90.2 R97.2 R98.1 R100.2 R101.1 R116.1 R118.2 R119.2 R120.2 R121.2 R122.2 R123.2 R124.2 R125.2 R126.2 R127.2 R128.1 R129.1 R145.1 R152.1 R176.2 R177.2 U3.4 U3.5 U5.11 U5.16 U6.11 U6.16 U7.7 U7.10 U7.11 U7.15 U8.14 U8.15 U9.5 U11.1 U12.1 U15.5 U17.5 U19.8 U20.3 U21.5 U22.5 U24.8 U25.3 U26.5 U28.1 U29.1 U30.5 U31.1 U33.1 U34.5 U36.8 U38.1 U38.2 U38.7 U38.8 U38.16 U39.1 U39.2 U39.8 U39.16 U42.1 U42.5 U43.8@1189.44,2127.4 U44.21 U47.15 U48.14 U52.14 U53.1 U53.2 U53.8 U53.16 U55.1 | length 552.8
  Top Layer w8: v1(1437.36,1978.22) 1440.07,1978.22 1447.83,1970.46 C145.2@1455.55,1970.46 ; v1@1592.76,189.86 v1(1592.76,194.86) ; v1@1592.76,244.86 v1(1592.76,249.86)
  Top Layer w18: v1(1937,350.61) U15.5@1977,350.61
  Bottom Layer w5: C65.2@1016.14,1044.15 v1(1016.14,1049.15) ; v1(1120.82,2606.41) U42.1@1120.82,2611.41 ; v1(1136.57,2246.14) U38.2@1136.57,2251.14 ; U38.7@1136.57,2349.56 v1(1136.57,2354.56) ; v1(1136.57,2446.14) U39.2@1136.57,2451.14 ; v1(1167,2365.31) U38.8@1172,2365.31 ; v1(1167,2565.31) U39.8@1172,2565.31 ; U42.5@1242.87,2670.47 v1(1242.87,2675.47) ; v1(2482.41,744.13) U6.11@2502.41,744.13 ; U5.11@2628.79,949.26 v1(2628.79,984.26)
  Bottom Layer w8: R152.1@1095.32,2026.92 v1(1095.32,2035.58) ; v1(1136.57,1921.14) U53.2@1136.57,1926.14 ; v1(1163.34,2040.31) U53.8@1172,2040.31 ; v1(1437.36,1978.22) 1440.07,1978.22 1445.07,1983.22 U52.14@1467.36,1983.22 ; R145.1@1529.29,2278.99 v1(1529.29,2287.66) ; Q2.3@1592.76,189.86 v1(1592.76,194.86) ; Q3.3@1592.76,244.86 v1(1592.76,249.86) ; v1(1642.36,2414.99) 1642.36,2411.48 1647.36,2406.48 U48.14@1647.36,2384.99 ; U47.15@1701.57,2192.38 v1(1710.23,2192.38) ; R128.1@2373.34,420.59 v1(2408.34,420.59) ; v1(2442.29,704.76) U6.16@2447.29,704.76 ; v1(4804.01,2305.14) R177.2@4809.01,2305.14 ; U55.1@4900.11,2332.1 v1(4905.11,2332.1) ; C217.2@4930.11,2332.1 v1(4930.11,2337.1)
  Bottom Layer w9: v1(2423.67,864.3) U7.7@2423.67,884.3 ; U7.15@2443.35,994.53 v1(2443.35,1014.53)
  Bottom Layer w12: C14.1@2343.39,929.57 C14.1@2348.39,929.57 ; C13.1@2343.39,949.26 C13.1@2348.39,949.26 ; v1(2351.29,479.64) R127.2@2356.29,479.64 ; R17.2@2351.39,994.99 v1(2351.39,999.99) ; C18.1@2412.29,704.76 v1(2417.29,704.76) ; R119.2@2426.92,557.77 v1(2426.92,562.77) ; R120.2@2449.61,597.77 v1(2449.61,602.77) ; R129.1@2456.47,302.13 v1(2461.47,302.13) ; R121.2@2472.29,557.77 v1(2472.29,562.77) ; R122.2@2494.98,597.77 v1(2494.98,602.77) ; R18.2@2515.63,990.99 v1(2515.63,995.99) ; R123.2@2517.66,557.77 v1(2517.66,562.77) ; R124.2@2540.35,597.77 v1(2540.35,602.77) ; v1(2556.87,537.41) R125.2@2561.87,537.41 ; R126.2@2621.07,498.34 v1(2626.07,498.34) ; v1(2652.46,691.05) R19.2@2652.46,696.05 ; C15.1@2668.16,859.24 v1(2673.16,859.24) ; v1(2668.16,889.14) U5.16@2668.16,894.14 ; v1(2686.08,769.22) C17.1@2691.08,769.22 ; v1(2686.08,789.97) C16.1@2691.08,789.97
  Bottom Layer w16: v1(1016.14,1049.15) U17.5@1041.34,1049.15 ; U22.5@1249.3,1771.24 v1(1249.3,1796.44) ; v1(1542.44,1244.12) U21.5@1542.44,1271.32
  other v1: 5951.96,101.4 1538.65,435.45 940.09,664.79 960.09,664.79 980.09,664.79 1465.29,672 940.09,684.79 960.09,684.79 980.09,684.79 1789.17,694.83 1038.3,803 1071.89,803 1623.36,835.18 1723.36,835.18 209.44,888.8 389.38,912.11 2358.39,931.57 2348.39,946.26 1103.06,988.88 1128.06,988.88 1465.29,1042 1789.17,1064.83 1053.15,1175.76 1623.37,1205.18 1723.36,1205.18 1363.59,1300.48 82.17,1305.75 1634.95,1311.67 1363.59,1325.48 82.8,1419.75 1257.87,1482.89 1282.87,1482.89 1257.87,1508.48 1282.87,1508.48 329.41,1524.51 1014.02,1572.61 1209.93,1644.63 389.38,1703.64 1719.79,1750.01 1249.64,1776.44 1518.4,1794.49 1269.3,1796.78 1289.3,1797.12 1518.4,1819.49 1172,1895.39 1157,1910.39 1189.44,2127.4 865.71,2154.05 757.24,2160.02 776.63,2196.02 747.88,2202.71 1172,2220.39 1157,2235.39 149.94,2305.66 169.94,2305.66 149.94,2325.66 169.94,2325.66 776.93,2395.44 816.3,2395.44 1172,2420.39 1157,2435.39 1642.36,2441.29 4860.74,2454.11 696.58,2661.73 721.58,2661.73 746.58,2661.73 771.57,2661.73 796.57,2661.73
3p8V: C45.2 C46.2 C66.2 C67.2 C74.2 C75.2 C105.2 C106.2 FB2.2 pad.1@992.61,1368.8 PP13.1 R40.2 R91.2 U18.3 U23.3 U35.1 U35.2 | length 643.2
  Top Layer w8: R91.2@1701.09,1289.11 1701.09,1289.43 1706.93,1295.28 1717.55,1295.28 v1(1728.85,1306.58)
  Top Layer w10: v1(389.38,1771.64) 449.31,1771.64 495.19,1725.75 950.99,1725.75 962.56,1737.32 PP13.1@970.09,1737.32 PP13.1@973.63,1737.32
  other v1: 1166.54,1186.2 1186.77,1186.68 1146.3,1190.61 1321.36,1680.22 1341.59,1680.69 1301.11,1684.63
  other v2: 926.09,1696.01 956.09,1696.01 986.09,1696.01 926.09,1736.73 926.09,1777.89 956.09,1777.89 986.09,1777.89
3SRX_DUT_n: C189.1 U1.B5 | length 288.3
  Bottom Layer w3.4: 4416.56,1125.75 4425.16,1125.75 4434.27,1116.64 4434.27,1098.95
  Bottom Layer w3.5: v1(4386.98,1141.5) 4388.95,1139.53 4398.17,1139.53 4411.95,1125.75 4416.55,1125.75
  Bottom Layer w5.6: 4434.32,1099 4443.87,1090.2
  Bottom Layer w6.3: 4444.46,1089.61 4444.46,1086.08 ccw(c4487.95,1086.08) 4487.95,1042.6 4607.36,1042.6 cw(c4607.36,1037) C189.1@4612.96,1037
3SRX_DUT_p: C188.1 U1.B4 | length 269.4
  Bottom Layer w3.4: 4448.05,1125.75 4456.65,1125.75 4465.77,1116.64 4465.77,1098.95
  Bottom Layer w3.5: v1(4418.48,1141.5) 4420.44,1139.53 4429.66,1139.53 4443.45,1125.75 4448.05,1125.75
  Bottom Layer w5.6: 4456.86,1090.29 4465.77,1098.95 4465.82,1099
  Bottom Layer w6.3: 4456.26,1089.69 4456.26,1086.08 ccw(c4487.95,1086.08) 4487.95,1054.4 4607.36,1054.4 ccw(c4607.36,1060) C188.1@4612.96,1060
3SRX_n: C189.2 J1.A35 | length 1518.6
  Bottom Layer w6.3: C189.2@4635.01,1037 cw(c4640.61,1037) 4640.61,1042.6 5000.07,1042.6 cw(c5000.07,942.6) 5070.78,1013.31 5244.62,839.47 ccw(c5323.68,918.52) 5323.68,806.72 5862.85,806.72 cw(c5862.85,786.34) 5873.57,803.67 5874.09,803.35 cw(c5864.01,787.07) 5883.13,788.23 5883.22,786.72 cw(c5876.93,786.34) 5883.23,786.34 5883.23,680.65 ccw(c5907.71,680.65) 5907.71,656.17 cw(c5907.71,649.86) 5914.01,649.86 J1.A35@5914.01,637.07
3SRX_p: C188.2 J1.A34 | length 1518.5
  Bottom Layer w6.3: C188.2@4635.01,1060 ccw(c4640.61,1060) 4640.61,1054.4 5000.07,1054.4 cw(c5000.07,942.6) 5079.12,1021.65 5252.97,847.81 ccw(c5323.68,918.52) 5323.68,818.52 5862.85,818.52 cw(c5862.85,786.34) 5895.03,786.34 5895.03,680.65 ccw(c5907.71,680.65) 5907.71,667.97 ccw(c5907.71,674.27) 5914.01,674.27 J1.A34@5914.01,687.07
4SRX_DUT_n: C193.1 U1.C1 | length 85
  Top Layer w6.3: U1.C1@4512.96,1172.99 cw(c4522.81,1172.99) 4522.81,1182.84 4583.51,1182.84 cw(c4583.51,1177.19) C193.1@4589.16,1177.19
4SRX_DUT_p: C191.1 U1.D1 | length 85
  Top Layer w6.3: U1.D1@4512.96,1204.49 ccw(c4522.81,1204.49) 4522.81,1194.64 4583.61,1194.64 ccw(c4583.61,1200.19) C191.1@4589.16,1200.19
4SRX_n: C193.2 J1.Y31 | length 1577.9
  Top Layer w6.3: C193.2@4611.21,1177.19 cw(c4616.81,1177.19) 4616.81,1182.79 4695.8,1182.79 cw(c4695.8,1082.79) 4766.51,1153.5 4930.1,989.92 ccw(c5009.15,1068.97) 5009.15,957.17 5852.7,957.17 cw(c5852.7,927.25) 5882.63,927.25 5882.63,894.62 ccw(c5921.08,894.62) 5921.08,856.17 6006.65,856.17 cw(c6006.65,848.8) 6014.01,848.8 v1(6014.01,837.07)
4SRX_p: C191.2 J1.Y30 | length 1577.9
  Top Layer w6.3: C191.2@4611.21,1200.19 ccw(c4616.81,1200.19) 4616.81,1194.59 4695.8,1194.59 cw(c4695.8,1082.79) 4774.86,1161.84 4938.44,998.26 ccw(c5009.15,1068.97) 5009.15,968.97 5852.7,968.97 cw(c5852.7,927.25) 5894.43,927.25 5894.43,894.62 ccw(c5921.08,894.62) 5921.08,867.97 6006.65,867.97 ccw(c6006.65,875.33) 6014.01,875.33 v1(6014.01,887.07)
5SRX_DUT_n: C195.1 U1.C2 | length 85
  Bottom Layer w6.3: v1(4481.47,1172.99) cw(c4491.32,1172.99) 4491.32,1182.84 4552.07,1182.84 cw(c4552.07,1177.24) C195.1@4557.67,1177.24
5SRX_DUT_p: C194.1 U1.D2 | length 85
  Bottom Layer w6.3: v1(4481.47,1204.49) ccw(c4491.32,1204.49) 4491.32,1194.64 4552.07,1194.64 ccw(c4552.07,1200.24) C194.1@4557.67,1200.24
5SRX_n: C195.2 J1.A31 | length 1483.9
  Bottom Layer w6.3: C195.2@4579.72,1177.24 cw(c4585.31,1177.24) 4585.31,1182.84 4958.24,1182.84 cw(c4958.24,1082.84) 5028.95,1153.55 5306.29,876.21 ccw(c5354.73,924.65) 5354.73,856.14 5862.06,856.12 ; 5864.01,856.12 5862.06,856.12 ; J1.A31@5914.01,837.07 5914.01,849.86 ccw(c5907.71,849.86) 5907.71,856.17 5865.94,856.17 ccw(c5865.94,849.87) 5865.61,856.16 cw(c5864.01,887.07) 5865.55,856.16 ccw(c5864.01,837.07) 5862.06,856.12
5SRX_p: C194.2 J1.A30 | length 1524.6
  Bottom Layer w6.3: C194.2@4579.72,1200.24 ccw(c4585.31,1200.24) 4585.31,1194.64 4958.24,1194.64 cw(c4958.24,1082.84) 5037.29,1161.89 5314.65,884.53 ccw(c5354.71,924.59) 5354.71,867.94 ; 5354.73,867.97 5412.13,867.97 cw(c5412.08,849.87) 5413.02,867.94 ccw(c5414.01,887.07) 5414.01,867.92 ; 5371.35,867.92 5414.01,867.92 ; J1.A30@5914.01,887.07 5914.01,874.27 cw(c5907.71,874.27) 5907.71,867.97 5865.94,867.97 ccw(c5865.94,849.87) 5865.13,867.95 ccw(c5865.35,862.05) 5865.05,867.95 cw(c5864.01,887.07) 5864.01,867.92 5414.01,867.92
"5V Fan": C8.2 R6.2 U4.5
6SRX_DUT_n: C198.1 U1.F1 | length 85
  Top Layer w6.3: U1.F1@4512.96,1267.48 cw(c4522.81,1267.48) 4522.81,1277.33 4583.51,1277.33 cw(c4583.51,1271.68) C198.1@4589.16,1271.68
6SRX_DUT_p: C196.1 U1.G1 | length 85
  Top Layer w6.3: U1.G1@4512.96,1298.98 ccw(c4522.81,1298.98) 4522.81,1289.13 4583.61,1289.13 ccw(c4583.61,1294.68) C196.1@4589.16,1294.68
6SRX_n: C198.2 J1.Z29 | length 1509.1
  Top Layer w6.3: C198.2@4611.21,1271.68 cw(c4616.81,1271.68) 4616.81,1277.28 4821.73,1277.28 cw(c4821.73,1177.28) 4892.44,1247.99 4942.16,1198.27 5111.03,1029.4 ccw(c5169.79,1088.15) 5169.79,1005.06 5917.93,1005.06 cw(c5917.93,990.01) 5932.98,990.01 5932.98,979.84 ccw(c5956.65,979.84) 5956.65,956.17 cw(c5956.65,948.8) 5964.01,948.8 v1(5964.01,937.07)
6SRX_p: C196.2 J1.Z28 | length 1509.1
  Top Layer w6.3: C196.2@4611.21,1294.68 ccw(c4616.81,1294.68) 4616.81,1289.08 4821.73,1289.08 cw(c4821.73,1177.28) 4900.79,1256.33 5119.38,1037.74 ccw(c5169.79,1088.15) 5169.79,1016.86 5917.93,1016.86 cw(c5917.93,990.01) 5944.78,990.01 5944.78,979.84 ccw(c5956.65,979.84) 5956.65,967.97 ccw(c5956.65,975.33) 5964.01,975.33 v1(5964.01,987.07)
7SRX_DUT_n: C200.1 U1.F2 | length 85
  Bottom Layer w6.3: v1(4481.47,1267.48) cw(c4491.32,1267.48) 4491.32,1277.33 4552.07,1277.33 cw(c4552.07,1271.73) C200.1@4557.67,1271.73
7SRX_DUT_p: C199.1 U1.G2 | length 85
  Bottom Layer w6.3: v1(4481.47,1298.98) ccw(c4491.32,1298.98) 4491.32,1289.13 4552.07,1289.13 ccw(c4552.07,1294.73) C199.1@4557.67,1294.73
7SRX_n: C200.2 J1.B29 | length 1429.7
  Bottom Layer w6.3: C200.2@4579.72,1271.73 cw(c4585.31,1271.73) 4585.31,1277.33 4964.09,1277.33 cw(c4964.09,1177.33) 5034.8,1248.04 5306.79,976.04 ccw(c5354.77,1024.02) 5354.77,956.17 5857.71,956.17 cw(c5857.71,949.86) 5864.01,949.86 J1.B29@5864.01,937.07
7SRX_p: C199.2 J1.B28 | length 1429.7
  Bottom Layer w6.3: C199.2@4579.72,1294.73 ccw(c4585.31,1294.73) 4585.31,1289.13 4964.09,1289.13 cw(c4964.09,1177.33) 5043.14,1256.38 5315.14,984.38 ccw(c5354.77,1024.02) 5354.77,967.97 5857.71,967.97 ccw(c5857.71,974.27) 5864.01,974.27 J1.B28@5864.01,987.07
8SRX_DUT_n: C202.1 U1.U7 | length 376.9
  Bottom Layer w6.3: v1(4323.99,1613.94) cw(c4323.99,1623.78) 4314.14,1623.78 4314.14,1631.41 cw(c4330.56,1631.41) 4318.95,1643.02 4321.26,1645.33 cw(c4334.92,1631.66) 4334.92,1650.98 ccw(c4334.92,1681.24) 4356.32,1659.85 4431.2,1734.73 cw(c4501.91,1664.02) 4501.91,1764.02 4607.37,1764.02 cw(c4607.37,1758.42) C202.1@4612.97,1758.42
8SRX_DUT_p: C201.1 U1.U8 | length 395.4
  Bottom Layer w6.3: v1(4292.49,1613.94) ccw(c4292.49,1623.78) 4302.34,1623.78 4302.34,1631.41 cw(c4330.56,1631.41) 4310.61,1651.36 4312.91,1653.67 cw(c4334.92,1631.66) 4334.92,1662.78 ccw(c4334.92,1681.24) 4347.97,1668.19 4422.86,1743.08 cw(c4501.91,1664.02) 4501.91,1775.82 4607.37,1775.82 ccw(c4607.37,1781.42) C201.1@4612.97,1781.42
8SRX_n: C202.2 R241.2 R242.2 | length 412.5
  Bottom Layer w6.3: C202.2@4635.25,1758.42 cw(c4640.85,1758.42) 4640.85,1764.02 4886.3,1764.02 ccw(c4886.3,1801.4) 4912.73,1774.97 cw(c4943.42,1744.28) 4943.42,1787.68 5029.41,1787.68 cw(c5029.41,1782.08) R241.2@5035.01,1782.08
8SRX_p: C201.2 R239.2 R240.2 | length 412.5
  Bottom Layer w6.3: C201.2@4635.25,1781.42 ccw(c4640.85,1781.42) 4640.85,1775.82 4886.3,1775.82 ccw(c4886.3,1801.4) 4904.38,1783.31 cw(c4943.42,1744.28) 4943.42,1799.48 5029.41,1799.48 ccw(c5029.41,1805.08) R239.2@5035.01,1805.08
9SRX_DUT_n: C204.1 U1.T7 | length 512.3
  Bottom Layer w3.4: 4276.7,1624.99 4276.7,1607.3 4285.81,1598.19 4294.41,1598.19
  Bottom Layer w3.5: 4294.42,1598.19 4299.02,1598.19 4312.8,1584.41 4322.02,1584.41 v1(4323.99,1582.44)
  Bottom Layer w5.6: 4267.14,1634.29 4267.73,1633.7 4276.7,1624.99
  Bottom Layer w6.3: 4267.14,1634.29 4267.14,1637.9 cw(c4300.3,1637.9) 4276.85,1661.36 4315.11,1699.61 cw(c4335.09,1679.63) 4335.09,1707.89 ccw(c4335.09,1752.06) 4366.32,1720.82 4427.57,1782.07 cw(c4498.28,1711.36) 4498.28,1811.36 4607.36,1811.36 cw(c4607.36,1805.76) C204.1@4612.96,1805.76
9SRX_DUT_p: C203.1 U1.T8 | length 530.2
  Bottom Layer w3.4: 4245.2,1624.99 4245.2,1607.3 4254.31,1598.19 4262.92,1598.19
  Bottom Layer w3.5: 4262.92,1598.19 4267.52,1598.19 4281.31,1584.41 4290.53,1584.41 v1(4292.49,1582.44)
  Bottom Layer w5.6: 4245.2,1624.99 4254.75,1633.78 4255.34,1634.38
  Bottom Layer w6.3: 4255.34,1634.38 4255.34,1637.9 cw(c4300.3,1637.9) 4268.51,1669.7 4272.68,1673.87 ; 4273.46,1674.65 4306.76,1707.95 ; 4306.77,1707.96 cw(c4335.09,1679.63) 4335.09,1719.69 ccw(c4335.09,1752.06) 4357.98,1729.17 4419.23,1790.42 cw(c4498.28,1711.36) 4498.28,1823.16 4607.36,1823.16 ccw(c4607.36,1828.76) C203.1@4612.96,1828.76
9SRX_n: C204.2 J1.C3 | length 1372.2
  Bottom Layer w6.3: C204.2@4635.01,1805.76 cw(c4640.61,1805.76) 4640.61,1811.36 4759.12,1811.36 ccw(c4759.12,1923.16) 4838.17,1844.11 4856.69,1862.63 5218.12,2224.05 5220.94,2226.88 cw(c5291.65,2156.17) 5291.65,2256.17 5804.1,2256.17 cw(c5804.1,2246.25) 5814.01,2246.25 J1.C3@5814.01,2237.07
9SRX_p: C203.2 J1.C2 | length 1372.2
  Bottom Layer w6.3: C203.2@4635.01,1828.76 ccw(c4640.61,1828.76) 4640.61,1823.16 4759.12,1823.16 ccw(c4759.12,1923.16) 4829.83,1852.45 4851.8,1874.43 5209.77,2232.4 5212.6,2235.22 cw(c5291.65,2156.17) 5291.65,2267.97 5804.1,2267.97 ccw(c5804.1,2277.88) 5814.01,2277.88 J1.C2@5814.01,2287.07
10SRX_DUT_n: C206.1 U1.U4 | length 281
  Bottom Layer w6.3: v1(4418.48,1613.94) cw(c4418.48,1623.78) 4408.63,1623.78 4408.63,1643.44 cw(c4459.28,1643.44) 4423.46,1679.26 4446.14,1701.94 cw(c4481.96,1666.12) 4481.96,1716.78 4607.37,1716.78 cw(c4607.37,1711.18) C206.1@4612.97,1711.18
10SRX_DUT_p: C205.1 U1.U5 | length 300
  Bottom Layer w6.3: v1(4386.98,1613.94) ccw(c4386.98,1623.78) 4396.83,1623.78 4396.83,1648.33 cw(c4447.48,1648.33) 4411.66,1684.15 4437.81,1710.29 cw(c4481.96,1666.12) 4481.96,1728.58 4607.37,1728.58 ccw(c4607.37,1734.18) C205.1@4612.97,1734.18
10SRX_n: C206.2 R237.2 R238.2 | length 412.8
  Bottom Layer w6.3: C206.2@4635.25,1711.18 cw(c4640.85,1711.18) 4640.85,1716.78 4891.63,1716.78 cw(c4891.63,1680.81) 4917.07,1706.24 ; 4917.07,1706.24 ccw(c4951.99,1741.16) 4951.99,1691.78 5029.41,1691.78 cw(c5029.41,1686.18) R237.2@5035.01,1686.18
10SRX_p: C205.2 R233.2 R234.2 | length 412.8
  Bottom Layer w6.3: C205.2@4635.25,1734.18 ccw(c4640.85,1734.18) 4640.85,1728.58 4891.63,1728.58 cw(c4891.63,1680.81) 4925.41,1714.59 ccw(c4951.99,1741.16) 4951.99,1703.58 5029.41,1703.58 ccw(c5029.41,1709.18) R233.2@5035.01,1709.18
